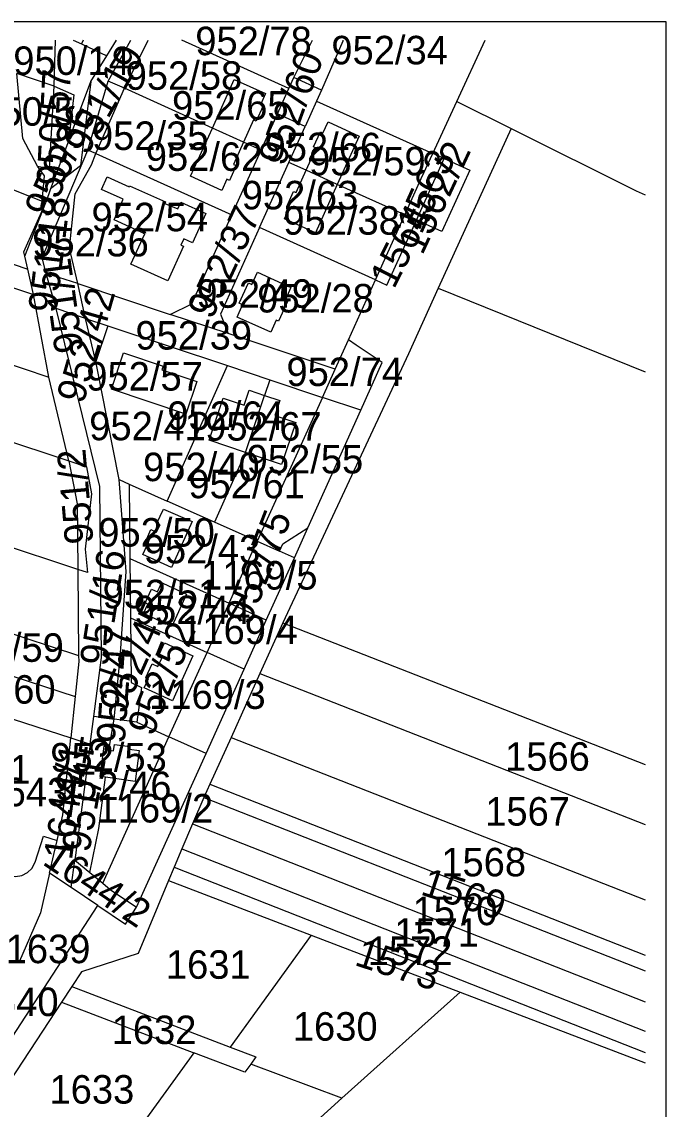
# Model space of a CAD drawing. Extents: x -583889 to -582839, y -1166553 to -1165065.
# Drawn here: x -582997 to -582838.7, y -1165334.9 to -1165067.8 of the extents above; entities that cross this region are included whole.
import ezdxf

# ---------------------------------------------------------------- set-up
doc = ezdxf.new("R2010")
doc.units = 0
for name, color, linetype in [('56', 7, 'Continuous'), ('Popis cest', 7, 'Continuous'), ('Vrstva 2', 7, 'Continuous')]:
    doc.layers.add(name, color=color, linetype=linetype)

msp = doc.modelspace()

# ---------------------------------------------------------------- linework, layer by layer
at = {"layer": '56'}
msp.add_lwpolyline([(-583888.67, -1166552.78), (-582838.67, -1166552.78), (-582838.67, -1165067.78), (-583888.67, -1165067.78), (-583888.67, -1166552.78)], dxfattribs=at)
at = {"layer": 'Vrstva 2'}
for p, q in [((-582989.08, -1165083.58), (-582988.75, -1165072.33)), ((-582984.37, -1165072.33), (-582982.3, -1165073.19)), ((-582981.88, -1165072.33), (-582982.3, -1165073.19)), ((-582976.11, -1165076.18), (-582973.7, -1165072.33)), ((-582975.77, -1165082.41), (-582970.18, -1165072.33)), ((-582971.76, -1165084.12), (-582965.95, -1165072.33)), ((-582931.41, -1165084.2), (-582957.66, -1165072.33)), ((-582890.14, -1165087.34), (-582883.2, -1165072.33)), ((-582982.3, -1165073.19), (-582976.11, -1165076.18)), ((-582980.01, -1165082.44), (-582976.11, -1165076.18)), ((-582989.08, -1165083.58), (-582998.19, -1165080.46)), ((-582985.55, -1165097.11), (-582980.01, -1165082.44)), ((-582980.74, -1165099.31), (-582975.77, -1165082.41)), ((-582971.76, -1165084.12), (-582975.77, -1165082.41)), ((-582950.17, -1165093.88), (-582944.82, -1165082)), ((-582931.41, -1165084.2), (-582930.18, -1165081.47)), ((-582923.35, -1165084.56), (-582930.18, -1165081.47)), ((-582978.82, -1165100.16), (-582971.76, -1165084.12)), ((-582950.17, -1165093.88), (-582971.76, -1165084.12)), ((-582934.2, -1165090.39), (-582931.41, -1165084.2)), ((-582923.35, -1165084.56), (-582924.6, -1165087.3)), ((-582924.6, -1165087.3), (-582927.38, -1165093.47)), ((-582924.6, -1165087.3), (-582896.05, -1165100.12)), ((-582896.05, -1165100.12), (-582890.14, -1165087.34)), ((-582890.14, -1165087.34), (-582876.77, -1165094.03)), ((-583044.73, -1165091.1), (-582992.03, -1165111.81)), ((-582938.21, -1165099.29), (-582934.2, -1165090.39)), ((-582927.38, -1165093.47), (-582934.2, -1165090.39)), ((-582955.52, -1165105.74), (-582950.17, -1165093.88)), ((-582942.51, -1165097.35), (-582950.17, -1165093.88)), ((-582940.04, -1165091.86), (-582942.51, -1165097.35)), ((-582931.38, -1165102.35), (-582927.38, -1165093.47)), ((-582876.77, -1165094.03), (-582894.67, -1165133.25)), ((-582985.55, -1165097.11), (-582989.97, -1165108.83)), ((-582978.82, -1165100.16), (-582980.74, -1165099.31)), ((-582945.4, -1165115.24), (-582938.21, -1165099.29)), ((-582942.51, -1165097.35), (-582944.97, -1165102.81)), ((-582938.21, -1165099.29), (-582942.51, -1165097.35)), ((-582978.82, -1165100.16), (-582945.4, -1165115.24)), ((-582938.58, -1165118.32), (-582931.38, -1165102.35)), ((-582927.13, -1165104.27), (-582931.38, -1165102.35)), ((-582900.07, -1165116.51), (-582893.22, -1165101.39)), ((-582893.22, -1165101.39), (-582896.05, -1165100.12)), ((-582919.49, -1165107.73), (-582927.13, -1165104.27)), ((-582902.93, -1165115.22), (-582919.49, -1165107.73)), ((-583050.67, -1165110.17), (-582995.55, -1165128.53)), ((-582989.97, -1165108.83), (-582991.1, -1165112.18)), ((-582996.24, -1165125.39), (-582991.1, -1165112.18)), ((-582991.1, -1165112.18), (-582992.03, -1165111.81)), ((-583052.33, -1165115.41), (-582994.16, -1165134.79)), ((-582910.14, -1165131.21), (-582902.93, -1165115.22)), ((-582902.93, -1165115.22), (-582900.07, -1165116.51)), ((-582910.14, -1165131.21), (-582938.58, -1165118.32)), ((-582995.55, -1165128.53), (-582996.24, -1165125.39)), ((-582994.16, -1165134.79), (-582995.55, -1165128.53)), ((-582983.24, -1165132.1), (-582990.97, -1165129.61)), ((-582988.54, -1165138.25), (-582990.97, -1165129.61)), ((-582916.77, -1165145.93), (-582910.14, -1165131.21)), ((-583057.74, -1165132.59), (-582990.33, -1165155.04)), ((-582983.24, -1165132.1), (-582960.56, -1165139.67)), ((-582981.35, -1165140.64), (-582983.24, -1165132.1)), ((-582894.67, -1165133.25), (-582843.89, -1165153.75)), ((-582990.33, -1165155.04), (-582994.16, -1165134.79)), ((-582981.35, -1165140.64), (-582988.54, -1165138.25)), ((-582946.28, -1165144.37), (-582960.56, -1165139.67)), ((-582981.35, -1165140.64), (-582975.89, -1165142.46)), ((-582978.82, -1165151.26), (-582981.35, -1165140.64)), ((-582975.89, -1165142.46), (-582978.82, -1165151.26)), ((-582975.89, -1165142.46), (-582946.46, -1165152.25)), ((-582920.02, -1165153.15), (-582946.28, -1165144.37)), ((-582920.02, -1165153.15), (-582916.77, -1165145.93)), ((-582973.05, -1165180.25), (-582978.82, -1165151.26)), ((-582961.29, -1165185.52), (-582946.46, -1165152.25)), ((-582946.46, -1165152.25), (-582936.08, -1165155.72)), ((-582923.13, -1165160.05), (-582920.02, -1165153.15)), ((-582985.47, -1165175.64), (-582990.33, -1165155.04)), ((-582936.08, -1165155.72), (-582937.36, -1165159.55)), ((-582936.08, -1165155.72), (-582923.13, -1165160.05)), ((-582942.04, -1165173.58), (-582937.36, -1165159.55)), ((-582923.13, -1165160.05), (-582939.16, -1165195.39)), ((-582913.72, -1165163.2), (-582923.13, -1165160.05)), ((-582926.73, -1165192.11), (-582913.72, -1165163.2)), ((-583019.35, -1165164.35), (-582985.47, -1165175.64)), ((-582942.04, -1165173.58), (-582949.68, -1165190.7)), ((-582973.05, -1165180.25), (-582970.66, -1165181.34)), ((-582970.66, -1165181.34), (-582961.29, -1165185.52)), ((-582970.66, -1165181.34), (-582970.47, -1165199.6)), ((-582983.21, -1165202.31), (-583027.19, -1165187.87)), ((-582949.68, -1165190.7), (-582961.29, -1165185.52)), ((-582939.16, -1165195.39), (-582949.68, -1165190.7)), ((-582930.03, -1165199.46), (-582926.73, -1165192.11)), ((-582946.05, -1165210.63), (-582939.16, -1165195.39)), ((-582939.16, -1165195.39), (-582933.68, -1165197.83)), ((-582930.03, -1165199.46), (-582933.68, -1165197.83)), ((-582970.47, -1165199.6), (-582946.05, -1165210.63)), ((-582970.47, -1165199.6), (-582970.31, -1165214.18)), ((-582983.21, -1165202.31), (-582983.03, -1165223.42)), ((-582951.49, -1165222.68), (-582946.05, -1165210.63)), ((-582936.94, -1165214.75), (-582946.05, -1165210.63)), ((-583014.39, -1165213.12), (-582983.03, -1165223.42)), ((-582970.31, -1165214.18), (-582951.49, -1165222.68)), ((-582942.38, -1165226.8), (-582936.94, -1165214.75)), ((-582932.83, -1165215.38), (-582938.52, -1165227.88)), ((-582932.83, -1165215.38), (-582843.89, -1165250.24)), ((-583017.5, -1165222.52), (-582983.91, -1165233.54)), ((-582960.85, -1165243.41), (-582951.49, -1165222.68)), ((-582942.38, -1165226.8), (-582951.49, -1165222.68)), ((-582983.02, -1165224.92), (-582983.91, -1165233.54)), ((-582983.03, -1165223.42), (-582983.02, -1165224.92)), ((-582951.73, -1165247.52), (-582942.38, -1165226.8)), ((-582938.52, -1165227.88), (-582945.59, -1165243.55)), ((-582938.52, -1165227.88), (-582843.89, -1165264.98)), ((-582983.91, -1165233.54), (-582984.95, -1165243.7)), ((-582980.23, -1165245.22), (-582979.33, -1165238.45)), ((-582974.34, -1165239.11), (-582979.33, -1165238.45)), ((-582999.09, -1165239.08), (-582984.95, -1165243.7)), ((-582975.63, -1165246.73), (-582974.34, -1165239.11)), ((-582968.73, -1165239.86), (-582974.34, -1165239.11)), ((-582968.73, -1165239.86), (-582960.85, -1165243.41)), ((-582984.95, -1165243.7), (-582980.23, -1165245.22)), ((-582977.1, -1165279.37), (-582960.85, -1165243.41)), ((-582951.73, -1165247.52), (-582960.85, -1165243.41)), ((-582945.59, -1165243.55), (-582950.78, -1165255.07)), ((-582945.59, -1165243.55), (-582843.89, -1165283.5)), ((-582980.23, -1165245.22), (-582984, -1165273.74)), ((-582976.53, -1165246.61), (-582975.63, -1165246.73)), ((-582975.63, -1165246.73), (-582974.43, -1165246.89)), ((-582968.78, -1165285.24), (-582951.73, -1165247.52)), ((-582976.47, -1165253.37), (-582977.75, -1165253.2)), ((-582969.12, -1165254.38), (-582976.47, -1165253.37)), ((-582950.78, -1165255.07), (-582952.24, -1165258.31)), ((-582950.78, -1165255.07), (-582843.89, -1165297.05)), ((-582952.24, -1165258.31), (-582955.06, -1165264.82)), ((-582952.24, -1165258.31), (-582843.89, -1165300.92)), ((-582955.06, -1165264.82), (-582957.7, -1165270.97)), ((-582955.06, -1165264.82), (-582843.89, -1165308.55)), ((-582957.7, -1165270.97), (-582959.57, -1165275.47)), ((-582984.89, -1165280.42), (-582984, -1165273.74)), ((-582984, -1165273.74), (-582980.28, -1165276.78)), ((-582959.57, -1165275.47), (-582960.94, -1165278.74)), ((-582959.57, -1165275.47), (-582843.89, -1165320.95)), ((-582984.89, -1165280.42), (-582990.16, -1165276.9)), ((-582980.28, -1165276.78), (-582977.1, -1165279.37)), ((-582960.94, -1165278.74), (-582925.93, -1165292.14)), ((-582978.28, -1165284.82), (-582984.89, -1165280.42)), ((-583000.42, -1165318.79), (-582978.28, -1165284.82)), ((-582925.93, -1165292.14), (-582945.82, -1165319.61)), ((-582925.93, -1165292.14), (-582889.34, -1165306.14)), ((-582984.67, -1165304.74), (-582987.21, -1165308.59)), ((-582984.67, -1165304.74), (-582945.82, -1165319.61)), ((-582889.34, -1165306.14), (-582918.34, -1165332.17)), ((-582889.34, -1165306.14), (-582843.89, -1165323.47)), ((-582987.21, -1165308.59), (-583007.11, -1165338.81)), ((-582987.21, -1165308.59), (-582954.72, -1165321.03)), ((-582954.72, -1165321.03), (-582976.18, -1165350.65)), ((-582918.34, -1165332.17), (-582940.77, -1165323.79)), ((-582918.34, -1165332.17), (-582950.06, -1165360.65))]:
    msp.add_line(p, q, dxfattribs=at)
for points in [[(-582930.18, -1165081.47), (-582925.54, -1165072.33)], [(-582918.12, -1165072.33), (-582918.14, -1165072.56), (-582923.35, -1165084.56)], [(-582993.15, -1165103.26), (-582996.72, -1165096.42), (-582998.19, -1165080.46)], [(-582993.15, -1165103.26), (-582990.23, -1165103.85), (-582989.08, -1165083.58)], [(-582980.01, -1165082.44), (-582982.56, -1165103.14), (-582989.97, -1165108.83)], [(-582989.08, -1165083.58), (-582984.25, -1165085.74), (-582985.55, -1165097.11)], [(-582944.82, -1165082), (-582937.12, -1165085.44), (-582938.36, -1165088.19), (-582937.74, -1165088.47), (-582939.41, -1165092.16), (-582940.04, -1165091.86)], [(-582927.13, -1165104.27), (-582924.66, -1165098.8), (-582925.31, -1165098.51), (-582923.65, -1165094.83), (-582923.02, -1165095.14), (-582921.75, -1165092.39), (-582914.14, -1165095.87), (-582919.49, -1165107.73)], [(-582876.77, -1165094.03), (-582846.07, -1165109.29), (-582843.89, -1165110.31)], [(-582990.97, -1165129.61), (-582991.96, -1165125.8), (-582980.74, -1165099.31)], [(-582983.24, -1165132.1), (-582985.25, -1165123.41), (-582983.85, -1165110.01), (-582979.89, -1165102.93), (-582978.82, -1165100.16)], [(-582902.93, -1165115.22), (-582898.92, -1165106.32), (-582896.05, -1165100.12)], [(-582893.22, -1165101.39), (-582886.92, -1165104.22), (-582893.81, -1165119.33), (-582900.07, -1165116.51)], [(-582992.03, -1165111.81), (-582991.4, -1165105.65), (-582993.15, -1165103.26)], [(-582944.97, -1165102.81), (-582944.34, -1165103.1), (-582945.98, -1165106.78), (-582946.64, -1165106.48), (-582947.87, -1165109.21), (-582955.52, -1165105.74)], [(-582919.49, -1165107.73), (-582924.84, -1165119.61), (-582932.5, -1165116.15), (-582931.26, -1165113.41), (-582931.9, -1165113.12), (-582930.24, -1165109.44), (-582929.6, -1165109.74), (-582927.13, -1165104.27)], [(-582966.79, -1165119.85), (-582974.34, -1165116.44), (-582972.09, -1165111.35), (-582977.39, -1165109), (-582975.99, -1165105.9), (-582970.6, -1165108.3), (-582970.5, -1165108.08), (-582961.72, -1165112.05), (-582961.87, -1165112.38), (-582958.7, -1165113.74), (-582957.96, -1165112.11), (-582951.8, -1165114.89), (-582955.02, -1165122.06), (-582957.22, -1165121.09), (-582957.96, -1165122.66), (-582957.3, -1165122.94), (-582961.15, -1165131.41), (-582970.17, -1165127.32), (-582966.79, -1165119.85)], [(-582996.24, -1165125.39), (-582996.48, -1165124.32), (-582991.1, -1165112.18)], [(-582960.56, -1165139.67), (-582955.22, -1165137.06), (-582945.4, -1165115.24)], [(-582938.58, -1165118.32), (-582948.17, -1165139.62), (-582946.28, -1165144.37)], [(-582910.14, -1165131.21), (-582907.32, -1165132.49), (-582900.07, -1165116.51)], [(-582940.47, -1165132.28), (-582939.12, -1165129.28), (-582930.89, -1165133.05), (-582932.24, -1165136.04), (-582931.68, -1165136.3), (-582933.97, -1165141.32), (-582934.5, -1165141.04), (-582935.81, -1165144.05), (-582944.11, -1165140.3), (-582942.74, -1165137.31), (-582943.56, -1165136.93), (-582941.28, -1165131.9), (-582940.47, -1165132.28)], [(-582894.67, -1165133.25), (-582901.99, -1165149.31), (-582932.83, -1165215.38)], [(-582979.33, -1165238.45), (-582977.41, -1165223.93), (-582977.85, -1165181.94), (-582988.54, -1165138.25)], [(-582913.72, -1165163.2), (-582908.46, -1165151.5), (-582914.89, -1165147.19), (-582916.77, -1165145.93)], [(-582974.99, -1165158.05), (-582972.04, -1165149.13), (-582962.28, -1165152.37), (-582962.57, -1165153.3), (-582954.03, -1165156.15), (-582956.68, -1165164.16), (-582974.99, -1165158.05)], [(-582942.04, -1165173.58), (-582950.96, -1165170.59), (-582947.49, -1165160.26), (-582942.37, -1165161.98), (-582941.12, -1165158.29), (-582937.36, -1165159.55)], [(-582937.36, -1165159.55), (-582933.61, -1165160.8), (-582934.8, -1165164.5), (-582929.7, -1165166.23), (-582933.17, -1165176.55), (-582942.04, -1165173.58)], [(-582985.47, -1165175.64), (-582983.42, -1165186.22), (-582983.21, -1165202.31)], [(-582985.47, -1165175.64), (-582981.1, -1165177.09), (-582979.9, -1165183.76), (-582981.45, -1165197.3), (-582980.83, -1165203.08), (-582983.21, -1165202.31)], [(-582974.34, -1165239.11), (-582972.87, -1165224.02), (-582971.36, -1165202.84), (-582973.05, -1165180.25)], [(-582955.15, -1165190.49), (-582960.24, -1165201.83), (-582967.3, -1165198.63), (-582966.22, -1165196.34), (-582966.87, -1165196.06), (-582965.26, -1165192.53), (-582963.88, -1165193.14), (-582963.01, -1165191.38), (-582963.83, -1165190.95), (-582962.18, -1165187.47), (-582955.15, -1165190.49)], [(-582933.68, -1165197.83), (-582932.87, -1165196.01), (-582926.73, -1165192.11)], [(-582936.94, -1165214.75), (-582933.14, -1165206.34), (-582930.03, -1165199.46)], [(-582966.06, -1165210.82), (-582966.68, -1165210.54), (-582965.13, -1165207.15), (-582963.63, -1165207.79), (-582962.77, -1165205.86), (-582963.59, -1165205.48), (-582963.45, -1165205.17), (-582956.54, -1165208.35), (-582960.16, -1165216.31), (-582967.06, -1165213.11), (-582966.06, -1165210.82)], [(-582970.31, -1165214.18), (-582970.15, -1165230.11), (-582967.59, -1165231.27), (-582968.73, -1165239.86)], [(-582965, -1165225.47), (-582963.54, -1165226.12), (-582962.62, -1165224.12), (-582963.46, -1165223.76), (-582961.94, -1165220.34), (-582955, -1165223.49), (-582960, -1165234.55), (-582966.93, -1165231.41), (-582965.9, -1165229.13), (-582966.55, -1165228.87), (-582965, -1165225.47)], [(-582988.32, -1165268.87), (-582987.64, -1165265.86), (-582986.89, -1165262.6), (-582984.95, -1165243.7)], [(-582977.75, -1165253.2), (-582976.76, -1165245.68), (-582976.42, -1165245.73), (-582976.53, -1165246.61)], [(-582974.43, -1165246.89), (-582974.21, -1165245.31), (-582970.46, -1165245.81), (-582970.54, -1165246.49), (-582968.13, -1165246.78), (-582969.12, -1165254.38)], [(-582980.28, -1165276.78), (-582978.11, -1165265.9), (-582976.47, -1165253.37)], [(-583010.51, -1165274.01), (-583001.61, -1165276.92), (-583000.06, -1165277.42), (-582998.56, -1165277.7), (-582997.02, -1165277.49), (-582995.62, -1165276.78), (-582994.54, -1165275.76), (-582993.75, -1165274.23), (-582991.64, -1165267.79), (-582988.32, -1165268.87)], [(-582990.16, -1165276.9), (-582989.11, -1165272.32), (-582988.32, -1165268.87)], [(-582957.7, -1165270.97), (-582882.68, -1165300.48), (-582843.89, -1165315.74)], [(-582990.16, -1165276.9), (-582992.4, -1165286.65), (-582997.54, -1165298.5)], [(-582960.94, -1165278.74), (-582968.43, -1165296.62), (-582982.31, -1165301.15), (-582984.67, -1165304.74)], [(-582977.1, -1165279.37), (-582975.28, -1165280.91), (-582968.78, -1165285.24)], [(-582978.28, -1165284.82), (-582971.52, -1165289.44), (-582968.78, -1165285.24)], [(-582940.77, -1165323.79), (-582942.23, -1165325.81), (-582954.72, -1165321.03)], [(-582945.82, -1165319.61), (-582939.49, -1165322.02), (-582940.77, -1165323.79)]]:
    msp.add_lwpolyline(points, dxfattribs=at)

# ---------------------------------------------------------------- texts
at = {"layer": 'Popis cest'}
for s, p in [('952/78', (-582954.38, -1165075.99)), ('952/34', (-582920.95, -1165078.24)), ('950/14', (-582999.09, -1165080.84)), ('952/58', (-582971.48, -1165084.49)), ('950/5', (-583007.4, -1165093.31)), ('952/65', (-582960.09, -1165091.81)), ('952/35', (-582979.76, -1165099.27)), ('952/62', (-582966.53, -1165104.41)), ('952/66', (-582937.35, -1165102.05)), ('952/59', (-582926.41, -1165105.51)), ('952/63', (-582942.97, -1165113.86)), ('952/54', (-582979.87, -1165119.24)), ('952/38', (-582932.75, -1165120.08)), ('952/36', (-582994.43, -1165125.42)), ('952/49', (-582954.09, -1165138.04)), ('952/28', (-582939.16, -1165139.19)), ('952/39', (-582969.06, -1165148.3)), ('952/74', (-582931.98, -1165157.26)), ('952/57', (-582981.15, -1165158.37)), ('952/64', (-582961.25, -1165168.03)), ('952/41', (-582980.43, -1165170.57)), ('952/67', (-582951.95, -1165170.66)), ('952/55', (-582941.75, -1165178.72)), ('952/40', (-582967.21, -1165180.62)), ('952/61', (-582956.06, -1165184.82)), ('952/50', (-582978.21, -1165196.69)), ('952/43', (-582967.03, -1165200.82)), ('1169/5', (-582952.97, -1165207.25)), ('952/51', (-582977.16, -1165211.83)), ('952/44', (-582969.46, -1165215.74)), ('1169/4', (-582957.83, -1165220.62)), ('950/59', (-583015.29, -1165225)), ('950/60', (-583017.32, -1165235.27)), ('1169/3', (-582965.72, -1165236.56)), ('952/53', (-582990, -1165251.95)), ('1566', (-582878.26, -1165251.75)), ('1645/1', (-583023.47, -1165254.92)), ('952/46', (-582988.86, -1165258.96)), ('1643', (-583006.41, -1165260.47)), ('1169/2', (-582978.62, -1165264.47)), ('1567', (-582883.15, -1165265.23)), ('1568', (-582893.94, -1165277.69)), ('1570', (-582900.99, -1165289.69)), ('1571', (-582905.5, -1165294.99)), ('1639', (-583000.96, -1165299.02)), ('1572', (-582912.01, -1165299.45)), ('1631', (-582961.59, -1165302.85)), ('1640', (-583008.79, -1165312.01)), ('1632', (-582974.92, -1165318.89)), ('1630', (-582930.41, -1165318.05)), ('1633', (-582990.19, -1165333.51))]:
    msp.add_text(s, height=7, dxfattribs=at).set_placement(p)
for s, rotation, p in [('951/19', 60, (-582981, -1165100.86)), ('952/60', 70, (-582932.55, -1165103.52)), ('950/57', 87, (-582986.4, -1165108.18)), ('950/36', 66, (-582990.23, -1165116.38)), ('1563', 66, (-582898.79, -1165120.24)), ('1562/2', 65, (-582898.59, -1165125.32)), ('951/18', 83, (-582988.53, -1165139.51)), ('952/37', 65, (-582950.29, -1165141.17)), ('1564', 63, (-582905.56, -1165133.64)), ('951/17', 98, (-582981.83, -1165148.69)), ('952/42', 74, (-582981.86, -1165161.86)), ('951/2', 95, (-582979.36, -1165195.79)), ('952/75', 69, (-582940.85, -1165216.23)), ('951/16', 81, (-582975.93, -1165226.3)), ('952/45', 66, (-582971.94, -1165238.21)), ('952/47', 86, (-582971.7, -1165245.2)), ('952/52', 68, (-582964.82, -1165243.58)), ('951/15', 80, (-582980.4, -1165272.06)), ('1644/1', 82, (-582984.7, -1165273.87)), ('1644/2', 326, (-582992.2, -1165274.6)), ('1569', 342, (-582899.3, -1165282.09)), ('1573', 342, (-582915.52, -1165299.42))]:
    msp.add_text(s, height=7, rotation=rotation, dxfattribs=at).set_placement(p)

doc.saveas('drawing.dxf')
